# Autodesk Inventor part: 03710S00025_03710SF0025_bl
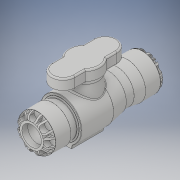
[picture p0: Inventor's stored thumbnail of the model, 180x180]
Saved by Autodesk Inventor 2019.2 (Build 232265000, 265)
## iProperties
Created: 2022-04
Part Number: 03710S00025_03710SF0025_bl
Material: Generic
Description: PA Ball Valve Series 1 25mm x 25mm
Document SubType Name: Modeling
Designer: Lenora
Density: 1 g/cm^3
Appearance: Default
Author: Lenora
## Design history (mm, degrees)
derived "037100.ipt"
feature "Solid1::037100.ipt" dims "ScaleForDerivedMember" = 10
tag "TaggingFeature1"
body "Solid1"
other parameters: "d" = 25 [user parameter], "A1" = 27 [user parameter], "A2" = 54 [user parameter], "E_" = 53 [user parameter], "E1" = 47 [user parameter], "d16" = 82.5 [user parameter], "d19" = 1 [user parameter], "d20" = 37.5 [user parameter], "d22" = 85 deg [user parameter], "d25" = 1 [user parameter], "d34" = 27 [user parameter], "d35" = 15 [user parameter], "d37" = 0 [user parameter], "d39" = 360 deg [user parameter], "d43" = 27 [user parameter], "d45" = 70 deg [user parameter], "d46" = 70 deg [user parameter], "d48" = 0 [user parameter], "d57" = 2 [user parameter], "d58" = 25 [user parameter], "d59" = 1 [user parameter], "d61" = 7.5 [user parameter], "d62" = 11.25 [user parameter], "d63" = 53 [user parameter], "d65" = 42.93 [user parameter], "d66" = 89 deg [user parameter], "d67" = 27 [user parameter], "d69" = 37.5 [user parameter], "d70" = 1.05 [user parameter], "d71" = 7.5 [user parameter], "d72" = 11.25 [user parameter], "d73" = 27 [user parameter], "d76" = 54 [user parameter], "d77" = 16.2 [user parameter], "d78" = 40.5 [user parameter], "d79" = 18.75 [user parameter], "d80" = 100 deg [user parameter], "d81" = 12.75 [user parameter], "d83" = 22.95 [user parameter], "d84" = 11.25 [user parameter], "d85" = 26.5 [user parameter], "d90" = 0 [user parameter], "d91" = 7.95 [user parameter], "d92" = 45 deg [user parameter], "d93" = 4.24 [user parameter], "d94" = 1.696 [user parameter], "d95" = 2.12 [user parameter], "d96" = 2.12 [user parameter], "d97" = 2.12 [user parameter], "d98" = 2.12 [user parameter], "d101" = 7.42 [user parameter], "d102" = 0 [user parameter], "d104" = 360 deg [user parameter], "d106" = 7.42 [user parameter], "d107" = 0 [user parameter], "d109" = 360 deg [user parameter], "d111" = 0.5 [user parameter], "d112" = 2 [user parameter], "d113" = 47 [user parameter]
